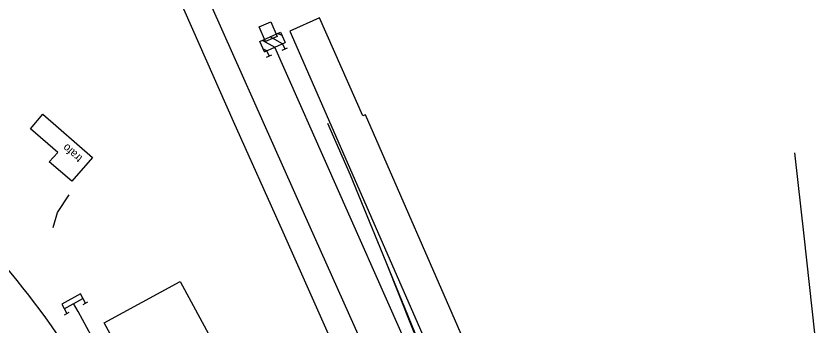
# Model space of a CAD drawing. Extents: x -496570 to -495506, y -1089156 to -1088046.
# Drawn here: x -496096.7 to -495946.2, y -1088429 to -1088371 of the extents above; entities that cross this region are included whole.
import ezdxf

# ---------------------------------------------------------------- set-up
doc = ezdxf.new("R2010")
doc.units = 0
for name, color, linetype in [('14', 7, 'Continuous'), ('35', 7, 'Continuous'), ('39', 7, 'Continuous'), ('PŮVODNÍ_NÁVRH', 7, 'Continuous'), ('SEE', 7, 'Continuous')]:
    doc.layers.add(name, color=color, linetype=linetype)

msp = doc.modelspace()

# ---------------------------------------------------------------- linework, layer by layer
at = {"layer": '14'}
for points in [[(-496031.216, -1088433.587), (-496042.641, -1088408.12), (-496063.79, -1088360.598), (-496069.753, -1088347.338)], [(-496016.532, -1088478.726), (-496026.498, -1088456.559), (-496035.879, -1088435.575), (-496046.648, -1088411.427), (-496055.896, -1088390.674), (-496071.432, -1088355.64)], [(-495984.212, -1088520.604), (-495987.937, -1088512.179), (-495995.163, -1088495.835), (-496007.326, -1088468.627), (-496015.768, -1088449.655), (-496024.81, -1088429.42), (-496048.198, -1088376.798)], [(-495940.564, -1088488.086), (-495943.541, -1088461.601), (-495948.995, -1088412.069), (-495950.732, -1088396.553)]]:
    msp.add_lwpolyline(points, dxfattribs=at)
for points in [[(-496074.283, -1088455.273), (-496090.055, -1088428.91), (-496108.418, -1088407.261), (-496129.685, -1088387.877)], [(-496060.305, -1088494.392), (-496069.107, -1088478.342), (-496082.819, -1088457.845), (-496098.833, -1088439.695), (-496101.304, -1088437.234), (-496120.979, -1088419.513)], [(-496072.447, -1088480.385), (-496086.263, -1088461.553), (-496102.223, -1088443.302), (-496125.575, -1088421.675)], [(-496059.857, -1088471.5), (-496072.678, -1088448.56), (-496085.881, -1088424.782)]]:
    msp.add_spline(points, degree=3, dxfattribs=at)
at = {"layer": '35'}
for p, q in [((-496051.013, -1088375.715), (-496047.115, -1088373.983)), ((-496047.602, -1088374.199), (-496046.855, -1088374.567)), ((-496047.115, -1088373.983), (-496046.249, -1088375.932)), ((-496050.147, -1088377.664), (-496051.013, -1088375.715)), ((-496050.526, -1088375.499), (-496048.198, -1088376.798)), ((-496050.147, -1088377.664), (-496046.249, -1088375.932)), ((-496046.736, -1088376.148), (-496049.064, -1088374.849)), ((-496049.66, -1088377.448), (-496050.407, -1088377.079)), ((-496049.227, -1088378.422), (-496049.66, -1088377.448)), ((-496049.66, -1088377.448), (-496049.66, -1088377.448)), ((-496046.791, -1088377.339), (-496045.816, -1088376.906)), ((-496046.736, -1088376.148), (-496046.303, -1088377.122)), ((-496049.714, -1088378.638), (-496048.739, -1088378.205)), ((-496087.63, -1088425.753), (-496084.132, -1088423.811)), ((-496084.084, -1088424.928), (-496083.21, -1088424.443)), ((-496087.581, -1088426.87), (-496086.707, -1088426.384))]:
    msp.add_line(p, q, dxfattribs=at)
msp.add_lwpolyline([(-496083.647, -1088424.685), (-496084.618, -1088422.937), (-496088.115, -1088424.879), (-496087.144, -1088426.627)], dxfattribs=at)
at = {"layer": '39'}
msp.add_line((-496005.336, -1088448.518), (-496031.21, -1088389.46), dxfattribs=at)
for points in [[(-496031.21, -1088389.46), (-496031.7, -1088389.65), (-496039.78, -1088371.31), (-496045.35, -1088373.79), (-496011.44, -1088451.19)], [(-496051.096, -1088372.969), (-496048.924, -1088372.04), (-496047.758, -1088374.798), (-496049.953, -1088375.726), (-496051.096, -1088372.969)], [(-496093.995, -1088392.062), (-496091.628, -1088389.343), (-496082.343, -1088397.431), (-496086.24, -1088401.888), (-496090.468, -1088398.223), (-496088.877, -1088396.516), (-496093.995, -1088392.062)], [(-496032.231, -1088482.763), (-496039.242, -1088486.597), (-496055.259, -1088457.292), (-496062.86, -1088443.337), (-496069.929, -1088447.197), (-496080.182, -1088428.388), (-496065.919, -1088420.663), (-496032.231, -1088482.763)]]:
    msp.add_lwpolyline(points, dxfattribs=at)
at = {"layer": 'PŮVODNÍ_NÁVRH'}
for points in [[(-496002.63, -1088476.82), (-496002.82, -1088476.02), (-496008.96, -1088461.03), (-496015.33, -1088446.34), (-496022.3, -1088429.58), (-496027.34, -1088417), (-496033.98, -1088400.73), (-496038.24, -1088391.07)], [(-496089.73, -1088410.52), (-496088.9, -1088407.75), (-496086.74, -1088404.4)]]:
    msp.add_lwpolyline(points, dxfattribs=at)
at = {"layer": 'SEE'}
msp.add_lwpolyline([(-496051.62, -1088524.39), (-496051.01, -1088524.72), (-496048.89, -1088527.16), (-496044.09, -1088523.58), (-496040.8, -1088521.19), (-496037.7, -1088519.67), (-496041.89, -1088512.27), (-496046.41, -1088504), (-496046.99, -1088501.65), (-496042.82, -1088499.36), (-496035.34, -1088494.54), (-496026.68, -1088488.94), (-496017.01, -1088483.74), (-496015.61, -1088482.89), (-496011.64, -1088481.25), (-496002.63, -1088476.82), (-496002.82, -1088476.02), (-496008.96, -1088461.03), (-496015.33, -1088446.34), (-496027.34, -1088417), (-496033.98, -1088400.73), (-496038.24, -1088391.07)], dxfattribs=at)

# ---------------------------------------------------------------- texts
at = {"layer": '39'}
msp.add_text('trafo', height=1.5, rotation=138.96819, dxfattribs=at).set_placement((-496084.124, -1088397.375))

doc.saveas('drawing.dxf')
